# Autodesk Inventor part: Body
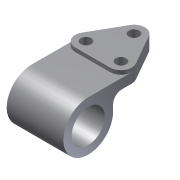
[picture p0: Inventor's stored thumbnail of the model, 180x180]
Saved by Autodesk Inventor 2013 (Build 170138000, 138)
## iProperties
Created: 2010-03
Part Number: Body
Document SubType Name: Modeling
Designer: bhakira
Density: 1 g/cm^3
Material: Generic
Author: bhakira
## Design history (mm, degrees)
sketch "Sketch1"
  geometry: L1 (10.853, 41.202)-(30.853, 6.202); L2 (-10.853, 41.202)-(-30.853, 6.202); L3 (-20, -12.5)-(20, -12.5); C1 r 6 at (0, 35); A1 r 12.5 centre (0, 35) between (10.853, 41.202) and (-10.853, 41.202); A2 r 12.5 centre (-20, 0) between (-30.853, 6.202) and (-20, -12.5); A3 r 12.5 centre (20, 0) between (20, -12.5) and (30.853, 6.202); 1 further point
  constraints: 6 end point, 6 point on circle, 6 tangent, 4 centre point, 3 horizontal alignment, 2 equal radius, 1 coincident, 1 vertical alignment, 1 other
  dimensions: "d25" = 35 vertical distance of A1.centre A2.centre; "d27" = 12.5 radius of A1; "d28" = 40 distance of A3.centre A2.centre; "d29" = 20 horizontal distance of A3.centre A1.centre
extrude "Extrusion1" new body sketch "Sketch1" distance "d6" = 15.875; taper "d7" = 0 deg
workplane "Work Plane2"
workplane "Work Plane3"
sketch "Sketch2"
  geometry: L1 (0, 11.375)-(0, 0); L2 (-12.5, 15.875)-(6.202, 15.875) reference; L3 (-50, 11.375)-(0, 11.375); L4 (0, 0)-(-11.5, 0); L5 (-21.5, -17.125)-(-21.5, -10); C1 r 19 at (-50, -17.125); A1 r 28.5 centre (-50, -17.125) between (-50, 11.375) and (-21.5, -17.125); A2 r 10 centre (-11.5, -10) between (-11.5, 0) and (-21.5, -10)
  constraints: 8 end point, 4 point on circle, 4 tangent, 3 centre point, 1 coincident, 1 perpendicular
  dimensions: "d9" = 38 diameter of C1; "d10" = 57 diameter of A1; "d11" = 50 distance from line of L1 C1.centre; "d12" = 33 distance from line of C1.centre L2; "d13" = 10 radius of A2
extrude "Extrusion2" join sketch "Sketch2" stored distance "d14" = 63.5; taper "d15" = 0 deg
sketch "Sketch3"
  geometry: C1 r 6 at (20, 0) reference; C2 r 6 at (-20, 0) reference; C3 r 6 at (0, 35); 1 further point
  constraints: 1 centre point
extrude "Extrusion3" cut sketch "Sketch3" distance "d16" = 63.5; taper "d17" = 0 deg
node "Sketch4"
hole "Hole1" diameter "d32" = 12; stored, may be unused: countersink angle "d36" = 90 deg, drill point angle "d38" = 118 deg; dims "d33" = 6, "d34" = 4, "d35" = 2082.8, "d37" = 8, "d39" = 10, "d40" = 10
body "Solid1"
